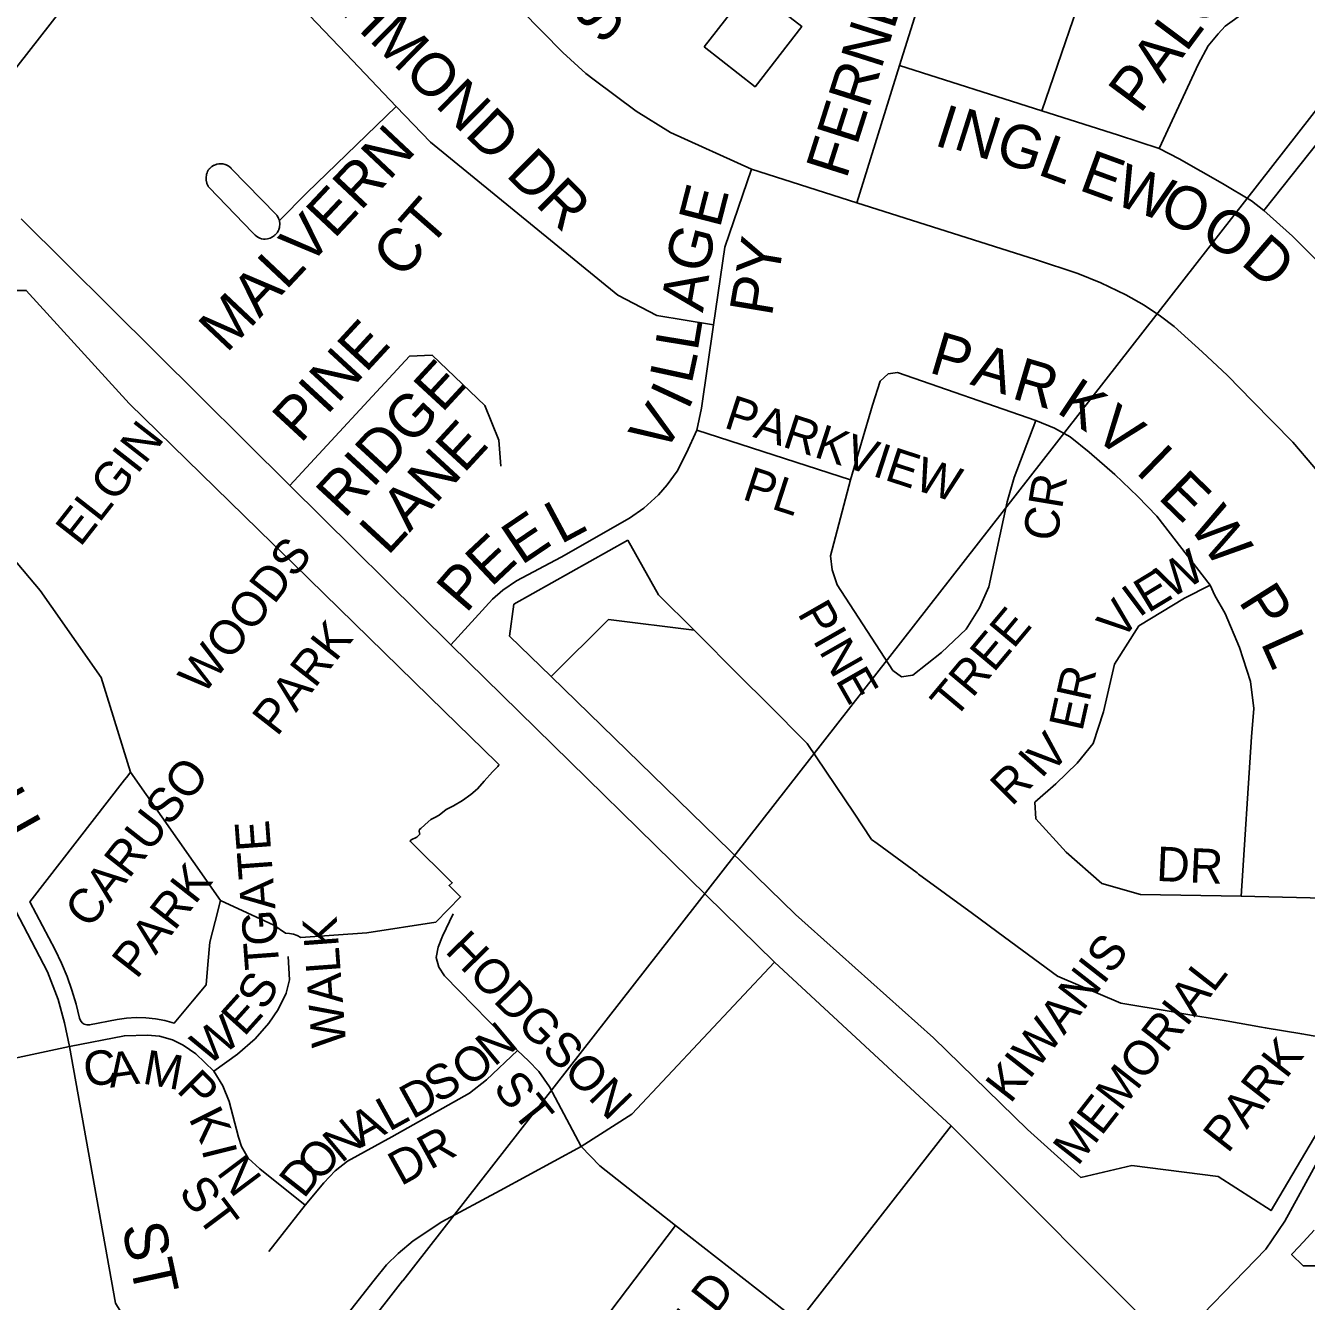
# Model space of a CAD drawing. Extents: x 586326 to 623965, y 4819854 to 4857850.
# Drawn here: x 601295 to 602038, y 4835757 to 4836497 of the extents above; entities that cross this region are included whole.
import ezdxf

# ---------------------------------------------------------------- set-up
doc = ezdxf.new("R2010")
doc.units = 0
for name, color, linetype in [('Lots_Concessions', 7, 'Continuous'), ('Major Rds and Hwys', 7, 'Continuous'), ('Minor Rd Lbls', 7, 'Continuous'), ('Minor Rds', 7, 'Continuous'), ('Park Lbls', 7, 'Continuous'), ('Park Outlines', 7, 'Continuous'), ('Private Rds', 7, 'Continuous'), ('Proposed Secondary Rds', 7, 'Continuous'), ('Pts of Interest', 7, 'Continuous'), ('School Syms_Lbls', 7, 'Continuous')]:
    doc.layers.add(name, color=color, linetype=linetype)

msp = doc.modelspace()

# ---------------------------------------------------------------- linework, layer by layer
at = {"layer": 'Lots_Concessions'}
for p, q in [((601513.73, 4835768.49), (602531.51, 4837073.55)), ((601254.45, 4836428.27), (601404.08, 4836620.12)), ((601396.49, 4835619.72), (601513.66, 4835768.55))]:
    msp.add_line(p, q, dxfattribs=at)
at = {"layer": 'Major Rds and Hwys'}
for points in [[(601292.3, 4836385.14), (601448.1, 4836230.37)], [(601448.1, 4836230.37), (601541.63, 4836137.87)], [(601541.63, 4836137.87), (601729.44, 4835953.61)], [(601729.44, 4835953.61), (601832.04, 4835858.52)], [(601832.04, 4835858.52), (601959.88, 4835730.4)]]:
    msp.add_lwpolyline(points, dxfattribs=at)
at = {"layer": 'Minor Rds'}
for points in [[(601802.14, 4836474.1), (601827.19, 4836554.24), (601837.33, 4836573.34), (601846.44, 4836584.72), (601872.59, 4836606.17), (601883.02, 4836617.63), (601907.63, 4836650.83), (601918.49, 4836667.11), (601922.49, 4836670.84), (601926.59, 4836672.3), (601930.13, 4836672.65), (601933.83, 4836671), (601940.91, 4836665.93), (601977.66, 4836638.47), (601983.35, 4836634.8), (601986.33, 4836632.51), (601987.93, 4836628.32), (601986.86, 4836623.35), (601984.05, 4836617.76), (601973.52, 4836604.41), (601947.37, 4836568.2), (601925.11, 4836549.46), (601914.24, 4836534.33), (601884.63, 4836447.87)], [(601509.99, 4836450.41), (601480.88, 4836480.84), (601425.73, 4836538.84), (601418.98, 4836543.6), (601415.37, 4836549.65), (601413.96, 4836554.17), (601415.4, 4836559.93), (601418.99, 4836564.53), (601424.33, 4836570.05), (601433.48, 4836583.07), (601441.63, 4836592.53), (601457.88, 4836608.42), (601470.85, 4836621.6)], [(601952.74, 4836425.9), (601975.71, 4836475.02), (601981.32, 4836485.58), (601987.1, 4836492.58), (601991.19, 4836497.02), (602015.75, 4836514.71), (602022.71, 4836520.63), (602027.14, 4836526.18), (602051.93, 4836560.15)], [(601777.39, 4836394.4), (601802.14, 4836474.1)], [(601884.63, 4836447.87), (601802.14, 4836474.1)], [(601509.99, 4836450.41), (601458.07, 4836400.27), (601442.12, 4836384.06)], [(601694.09, 4836323.66), (601661.26, 4836329.07), (601638.63, 4836340.85), (601529.77, 4836429.66), (601509.99, 4836450.41)], [(601952.74, 4836425.9), (601929.22, 4836433.77), (601884.63, 4836447.87)], [(602050.99, 4836436.91), (602013.47, 4836390.02)], [(602013.47, 4836390.02), (602006.36, 4836395.52), (601989.56, 4836405.69), (601964.4, 4836419.9), (601952.74, 4836425.9)], [(601442.12, 4836384.06), (601442.21, 4836383.64), (601442.35, 4836382.51), (601442.37, 4836382.3), (601442.37, 4836382.08), (601442.36, 4836381.87), (601442.27, 4836380.73), (601442.24, 4836380.52), (601442.2, 4836380.31), (601442.15, 4836380.11), (601441.81, 4836379.01), (601441.74, 4836378.81), (601441.66, 4836378.62), (601441.56, 4836378.43), (601441, 4836377.43), (601440.88, 4836377.23), (601440.75, 4836377.04), (601440.59, 4836376.86), (601439.7, 4836375.89), (601439.55, 4836375.74), (601439.21, 4836375.46), (601438.08, 4836374.59), (601436.8, 4836373.94), (601435.27, 4836373.52), (601433.84, 4836373.4), (601432.79, 4836373.4), (601431.64, 4836373.52), (601430.68, 4836373.84), (601429.94, 4836374.19), (601429.01, 4836374.79), (601427.96, 4836375.69), (601426.5, 4836377.13), (601401.26, 4836403.23), (601401.11, 4836403.41), (601400.97, 4836403.6), (601400.85, 4836403.8), (601400.74, 4836404.01), (601400.22, 4836405.15), (601400.14, 4836405.33), (601400.08, 4836405.5), (601400.03, 4836405.68), (601399.73, 4836406.91), (601399.69, 4836407.09), (601399.66, 4836407.27), (601399.64, 4836407.46), (601399.57, 4836408.72), (601399.56, 4836408.91), (601399.57, 4836409.09), (601399.59, 4836409.28), (601399.75, 4836410.53), (601399.78, 4836410.71), (601399.82, 4836410.9), (601399.88, 4836411.08), (601400.13, 4836411.86), (601400.43, 4836412.67)], [(601400.43, 4836412.67), (601400.82, 4836413.32), (601401.3, 4836413.96), (601401.41, 4836414.11), (601401.54, 4836414.26), (601401.68, 4836414.4), (601402.47, 4836415.15), (601402.61, 4836415.28), (601402.77, 4836415.4), (601402.93, 4836415.51), (601403.85, 4836416.08), (601404.02, 4836416.18), (601404.19, 4836416.27), (601404.37, 4836416.35), (601405.38, 4836416.74), (601405.57, 4836416.8), (601405.76, 4836416.85), (601405.95, 4836416.89), (601407.02, 4836417.08), (601407.21, 4836417.1), (601407.41, 4836417.12), (601407.6, 4836417.12), (601408.69, 4836417.09), (601408.9, 4836417.08), (601409.12, 4836417.05), (601409.33, 4836417), (601410.58, 4836416.69), (601410.8, 4836416.63), (601411.02, 4836416.55), (601411.23, 4836416.45), (601412.38, 4836415.86), (601412.58, 4836415.74), (601412.78, 4836415.61), (601412.96, 4836415.47), (601413.94, 4836414.63), (601414.05, 4836414.53), (601414.15, 4836414.43), (601440.41, 4836387.39), (601440.56, 4836387.23), (601440.69, 4836387.06), (601440.8, 4836386.89), (601441.4, 4836385.91), (601441.51, 4836385.73), (601441.6, 4836385.54), (601441.68, 4836385.34), (601442.12, 4836384.06)], [(601694.09, 4836323.66), (601700.77, 4836368.76), (601716.13, 4836414)], [(602063.02, 4836341.99), (602030.13, 4836375), (602013.47, 4836390.02)], [(601684.37, 4836262.45), (601687.13, 4836275.28), (601694.09, 4836323.66)], [(601448.1, 4836230.37), (601517.73, 4836305.48), (601530.77, 4836305.93), (601561.32, 4836276.82), (601569.54, 4836256.56), (601570.56, 4836241.53)], [(601881.25, 4836268.06), (601800.96, 4836295.94), (601795.46, 4836295.08), (601790.91, 4836290.91), (601786.47, 4836276.98), (601773.53, 4836233.62)], [(601541.63, 4836137.87), (601565.78, 4836164.27), (601571.75, 4836169.5), (601579.74, 4836174.89), (601605.65, 4836188.68), (601645.33, 4836211.36), (601653.67, 4836217.2), (601662.27, 4836224.92), (601667.21, 4836230.62), (601672.92, 4836238.67), (601678.4, 4836249.22), (601684.37, 4836262.45)], [(601773.53, 4836233.62), (601684.37, 4836262.45)], [(601881.25, 4836268.06), (601868.66, 4836234.99), (601864.62, 4836220.76), (601853.85, 4836171.51), (601848.48, 4836159.28), (601840.77, 4836146.94), (601826.54, 4836133.26), (601809.88, 4836120.18), (601803.31, 4836119.2), (601798.15, 4836122.9), (601765.83, 4836172.64), (601762.95, 4836181.33), (601761.94, 4836189.49), (601773.53, 4836233.62)], [(601982.44, 4836172.49), (601951.39, 4836212.46), (601940.33, 4836223.95), (601926.97, 4836236.68), (601912.11, 4836249.6), (601901.06, 4836258.57), (601892, 4836263.54), (601881.25, 4836268.06)], [(602000.35, 4835991.95), (601942.01, 4835992.87), (601919.5, 4835999.3), (601898.75, 4836017.47), (601881.13, 4836036.76), (601880.71, 4836046.41), (601892.86, 4836057.19), (601905.26, 4836069.13), (601914.45, 4836080.61), (601920.41, 4836098.9), (601926.85, 4836126.55), (601941, 4836148.8), (601967.48, 4836164.83), (601982.44, 4836172.49)], [(602000.35, 4835991.95), (602006.33, 4836084.29), (602007.7, 4836100.83), (602005.87, 4836116.45), (601999.44, 4836136.2), (601991.17, 4836155.95), (601985.19, 4836166.52), (601982.44, 4836172.49)], [(601277.3, 4836005.5), (601307.49, 4835947.86), (601313.77, 4835931.85), (601317.29, 4835918.25), (601320.26, 4835904.69)], [(602096.64, 4835989.53), (602000.35, 4835991.95)], [(601580.25, 4835902.34), (601537.94, 4835945.67), (601534.74, 4835950.72), (601533.05, 4835956.28), (601534.27, 4835962.24), (601536.86, 4835968.59), (601542.99, 4835981.65)], [(601404.01, 4835890.29), (601417.76, 4835900.13), (601428.04, 4835908.97), (601435.95, 4835918.06), (601441.43, 4835926.01), (601445.97, 4835935.63), (601448.03, 4835943.39), (601447.13, 4835956.86)], [(601218.4, 4835822.4), (601271.18, 4835890.01), (601275.12, 4835893.44), (601279.54, 4835895.85), (601320.26, 4835904.69)], [(601320.26, 4835904.69), (601352.19, 4835910.87), (601365.55, 4835911.14), (601372.52, 4835910.56), (601380.06, 4835908.55), (601386.32, 4835905.4), (601393.58, 4835900.31), (601404.01, 4835890.29)], [(601320.26, 4835904.69), (601346.95, 4835755.54), (601358.93, 4835735.95), (601374.57, 4835721.63), (601426.32, 4835680)], [(601580.25, 4835902.34), (601562.26, 4835885.33), (601552.38, 4835877.57), (601507.46, 4835852.17), (601481.62, 4835838.11), (601474.39, 4835832.33), (601467.84, 4835825.43), (601457.02, 4835812.57)], [(601617.3, 4835846.52), (601598.95, 4835881.1), (601592.63, 4835890.15), (601586.76, 4835896.29), (601580.25, 4835902.34)], [(601404.01, 4835890.29), (601409.35, 4835881.79), (601412.86, 4835872.65), (601418.35, 4835851.89), (601420.2, 4835846.57), (601424.07, 4835839.86), (601430.74, 4835833.56), (601457.02, 4835812.57)], [(601457.02, 4835812.57), (601435.96, 4835785.61)]]:
    msp.add_lwpolyline(points, dxfattribs=at)
at = {"layer": 'Park Outlines'}
for points in [[(601213.66, 4836275.56), (601303.16, 4836169.35), (601309.62, 4836160.16), (601338.72, 4836118.75), (601343.93, 4836101.98), (601355.77, 4836063.91), (601392, 4836012.09), (601407.93, 4835989.32), (601438.98, 4835975.03), (601445.62, 4835970.31), (601447.97, 4835970.23), (601450.28, 4835969.78), (601452.48, 4835968.97), (601454.54, 4835967.83), (601492.94, 4835970.6), (601532.85, 4835976.88), (601547.27, 4835991.46), (601540.61, 4835997.99), (601542.44, 4835999.71), (601517.95, 4836023.72), (601518.65, 4836024.51), (601521.87, 4836026.19), (601523.59, 4836027.81), (601523.27, 4836029.46), (601523.29, 4836029.89), (601523.51, 4836030.6), (601524.13, 4836031.17), (601526.49, 4836033.33), (601526.79, 4836033.58), (601530.1, 4836036.31), (601532.37, 4836037.54), (601534.87, 4836038.88), (601538.89, 4836042.15), (601543.23, 4836044.36), (601548.32, 4836047.38), (601553.23, 4836050.83), (601557.02, 4836054.24), (601560.91, 4836058.72), (601565.76, 4836064.08), (601568.84, 4836067.23), (601569.25, 4836067.72), (601569.64, 4836068.16), (601568.34, 4836069.44), (601537.65, 4836099.42), (601450.65, 4836184.43), (601438.37, 4836196.43), (601354.94, 4836277.96), (601295.21, 4836343.53), (601274.76, 4836343.46)], [(602059.83, 4835907.77), (602035.52, 4835911.92), (602014.36, 4835915.54), (602012.24, 4835915.9), (601991.65, 4835919.42), (601965.9, 4835923.82), (601962.87, 4835924.34), (601959.84, 4835924.85), (601930.53, 4835929.86), (601893.72, 4835945.48), (601863.09, 4835968.03), (601844.36, 4835981.8), (601813.18, 4836004.73), (601812.3, 4836005.38), (601789.06, 4836022.48), (601785.87, 4836024.82), (601775.69, 4836039.99), (601748.42, 4836080.6), (601725.23, 4836103.87), (601709.84, 4836119.28), (601682.88, 4836146.27), (601633.22, 4836152.51), (601599.91, 4836119.32), (601666.03, 4836055.01), (601741.66, 4835981.27), (601749.11, 4835974.6), (601821.76, 4835909.61), (601876.29, 4835856.41), (601907.36, 4835828.6), (601936.89, 4835835.43), (601987.07, 4835829.13), (602017.74, 4835809.3), (602074.45, 4835905.29)], [(602042.78, 4835797.89), (602036.65, 4835791.15), (602030.3, 4835784.61), (602029.62, 4835783.94), (602036.48, 4835777.21), (602123.18, 4835777.21)]]:
    msp.add_lwpolyline(points, dxfattribs=at)
for points in [[(601644.31, 4836198.64), (601578.28, 4836161.31), (601575.74, 4836142.82), (601599.91, 4836119.32), (601633.22, 4836152.51), (601682.88, 4836146.27), (601662.19, 4836166.9)], [(601355.23, 4836063.22), (601353.3, 4836060.77), (601352.27, 4836059.44), (601297.3, 4835988.63), (601311.87, 4835960.67), (601315.56, 4835953.08), (601318.83, 4835945.3), (601321.67, 4835937.35), (601324.08, 4835929.26), (601326.05, 4835921.05), (601326.6, 4835919.61), (601327.56, 4835918.4), (601328.85, 4835917.54), (601330.34, 4835917.12), (601331.89, 4835917.18), (601347.86, 4835920.28), (601353.39, 4835921.11), (601358.98, 4835921.46), (601364.58, 4835921.32), (601370.14, 4835920.71), (601375.63, 4835919.62), (601381.01, 4835918.06), (601391.65, 4835930.94), (601399.53, 4835940.5), (601400.6, 4835952.19), (601401.79, 4835965.16), (601404.86, 4835977.24), (601407.93, 4835989.32), (601392, 4836012.09), (601355.77, 4836063.91)]]:
    msp.add_lwpolyline(points, close=True, dxfattribs=at)
at = {"layer": 'Private Rds'}
for points in [[(601832.04, 4835858.52), (601743.37, 4835744.92)], [(601672, 4835800.68), (601628.12, 4835835.23), (601617.3, 4835846.52)], [(601672, 4835800.68), (601527.22, 4835609.68)], [(601743.37, 4835744.92), (601672, 4835800.68)]]:
    msp.add_lwpolyline(points, dxfattribs=at)
at = {"layer": 'Proposed Secondary Rds'}
for points in [[(601716.13, 4836414), (601669.19, 4836435.31), (601649.13, 4836447.65), (601624.84, 4836465.87), (601620.04, 4836469.47), (601606.67, 4836481.59), (601570.24, 4836518.91)], [(601777.39, 4836394.4), (601716.13, 4836414)], [(602054.88, 4836225.63), (602042.53, 4836241.1), (602030.47, 4836255.46), (602006.89, 4836279.27), (601992.42, 4836294.07), (601977.83, 4836307.96), (601961.48, 4836322.6), (601953.64, 4836328.58), (601944.04, 4836334.92), (601933.41, 4836341.04), (601918.92, 4836348), (601905.68, 4836353.4), (601881.03, 4836361.6), (601777.39, 4836394.4)], [(601729.44, 4835953.61), (601646.7, 4835865.34), (601617.3, 4835846.52)], [(601959.88, 4835730.4), (602014.71, 4835786.88), (602025.66, 4835803.23), (602045.61, 4835839.57), (602069.04, 4835878.86)], [(601617.3, 4835846.52), (601570.22, 4835821.03), (601536.44, 4835802.85), (601519.84, 4835791.78), (601511.05, 4835784.5), (601504.26, 4835777.79), (601497.11, 4835768.91), (601479.25, 4835746.39), (601426.32, 4835680)]]:
    msp.add_lwpolyline(points, dxfattribs=at)
at = {"layer": 'School Syms_Lbls'}
msp.add_lwpolyline([(601688.59, 4836484.91), (601715.86, 4836519.81), (601745.47, 4836496.68), (601718.2, 4836461.78)], close=True, dxfattribs=at)

# ---------------------------------------------------------------- texts
at = {"layer": 'Minor Rd Lbls'}
for s, height, rotation, p in [('PALGRAVE', 25.002, 53.3103, (601941.81, 4836445.54)), ('FERNDALE', 25.002, 72.39239, (601771.17, 4836407.69)), ('RICHMOND DR', 25.002, 315.35589, (601435.48, 4836546.1)), ('I', 25, 342.3499, (601821.48, 4836428.1)), ('N', 25, 342.3499, (601832.48, 4836426.1)), ('G', 25, 342.3499, (601856.48, 4836419.1)), ('MALVERN', 25.002, 46.73434, (601411.48, 4836306.74)), ('L', 25, 339.94392, (601881.48, 4836411.1)), ('E', 25, 339.94392, (601905.48, 4836402.1)), ('W', 25, 339.94392, (601925.48, 4836394.1)), ('E', 25, 75.61862, (601697.72, 4836379.12)), ('O', 25, 336.57133, (601951.48, 4836385.1)), ('CT', 25.002, 48.71593, (601513.03, 4836349.45)), ('O', 25, 326.88868, (601975.48, 4836374.1)), ('G', 25, 75.61862, (601689.75, 4836352.6)), ('PY', 25.002, 80.48687, (601727.9, 4836327.9)), ('D', 25, 319.26791, (601999.48, 4836359.1)), ('A', 25, 80.15651, (601687.9, 4836330.36)), ('PINE', 25.002, 47.29063, (601454.4, 4836254.24)), ('L', 25, 80.6111, (601684.86, 4836307.81)), ('P', 25, 343.54, (601818.48, 4836296.1)), ('L', 25, 77.79745, (601681.32, 4836288.65)), ('A', 25, 343.54, (601842.48, 4836289.1)), ('RIDGE', 25.002, 47.29063, (601479.77, 4836210.56)), ('R', 25, 343.54, (601866.48, 4836281.1)), ('K', 25, 326.30995, (601892.48, 4836273.1)), ('I', 25, 65.03111, (601679.26, 4836273.38)), ('V', 25, 56.49266, (601664.74, 4836247.69)), ('PARKVIEW', 19.998, 341.99586, (601699.48, 4836264.1)), ('V', 25, 322.52384, (601913.48, 4836259.1)), ('LANE', 25.002, 47.29063, (601505.05, 4836189.1)), ('I', 25, 315.85512, (601938.48, 4836238.1)), ('PL', 19.998, 341.99586, (601710.13, 4836222.56)), ('E', 25, 315.85512, (601951.48, 4836223.1)), ('CR', 19.998, 80.5377, (601893.22, 4836197.15)), ('L', 25, 28.17861, (601605.34, 4836195.94)), ('W', 25, 304.59231, (601969.48, 4836207.1)), ('E', 25, 34.08782, (601582.63, 4836183.69)), ('E', 25, 43.28438, (601564.95, 4836170.78)), ('W', 20, 31.21842, (601959.14, 4836164.11)), ('P', 25, 49.14464, (601550.4, 4836155.56)), ('E', 20, 31.21842, (601946.28, 4836155.96)), ('I', 20, 36.86992, (601941.15, 4836153.25)), ('P', 25, 302.19575, (601998.48, 4836163.1)), ('V', 19.96, 50.86992, (601930.78, 4836139.5)), ('PINE', 19.998, 299.7449, (601742.48, 4836156.1)), ('TREE', 19.998, 50.10981, (601833.88, 4836093.91)), ('L', 25, 294.22776, (602011.48, 4836139.1)), ('R', 19.99, 77.47121, (601912.37, 4836104.22)), ('E', 19.99, 77.47121, (601908.15, 4836087.05)), ('MILL', 25.002, 299.29138, (601251.48, 4836078.1)), ('V', 20, 48.94521, (601889.89, 4836062.11)), ('I', 20, 48.94521, (601884.41, 4836059.57)), ('R', 20, 45.00002, (601867.13, 4836043.58)), ('GATE', 19.998, 94.23641, (601441.36, 4835963.88)), ('DR', 19.998, 357.43078, (601950.87, 4836000.77)), ('WALK', 19.998, 94.23641, (601480.92, 4835904.92)), ('HODGSON', 19.998, 314.32598, (601537.63, 4835959.61)), ('T', 20, 94.23641, (601442.19, 4835949.91)), ('S', 20, 60.25514, (601433.83, 4835924.81)), ('E', 20, 48.01281, (601421.59, 4835909.85)), ('W', 20, 35.5377, (601400.28, 4835893.11)), ('N', 20, 39.80559, (601566.79, 4835892.47)), ('O', 20, 40.60131, (601552.66, 4835880.33)), ('C', 20, 8.88068, (601330.01, 4835880.89)), ('A', 20, 8.13012, (601343.83, 4835880.63)), ('M', 20, 349.69517, (601362.07, 4835883.22)), ('P', 20, 315.00002, (601381.82, 4835878.75)), ('S', 20, 30.96378, (601533.99, 4835871.27)), ('ST', 19.998, 308.65983, (601565.48, 4835880.34)), ('D', 20, 28.96768, (601519.35, 4835862.12)), ('L', 20, 28.96768, (601505.73, 4835854.92)), ('K', 20, 296.56507, (601389.11, 4835862.93)), ('A', 20, 28.96768, (601489.79, 4835845.85)), ('N', 20, 39.80559, (601478.09, 4835836.43)), ('DR', 19.998, 28.96768, (601512.68, 4835823.35)), ('I', 20, 284.03626, (601396.84, 4835844.99)), ('O', 20, 51.91125, (601466.12, 4835825.24)), ('N', 20, 306.86992, (601405.18, 4835831.41)), ('D', 20, 51.91125, (601456.26, 4835815.72)), ('ST', 19.998, 306.86992, (601383, 4835820.06)), ('ST', 25.002, 282.18865, (601350.48, 4835800.1))]:
    msp.add_text(s, height=height, rotation=rotation, dxfattribs=at).set_placement(p)
at = {"layer": 'Park Lbls'}
for s, p in [('ELGIN', (601326.54, 4836194.11)), ('WOODS', (601397.86, 4836108.09)), ('PARK', (601440.72, 4836084.05)), ('CARUSO', (601331.85, 4835972.26)), ('PARK', (601359.24, 4835943.18)), ('KIWANIS', (601866.41, 4835870.91)), ('MEMORIAL', (601905.52, 4835834.66)), ('PARK', (601992.64, 4835842.01))]:
    msp.add_text(s, height=19.992, rotation=52.00002, dxfattribs=at).set_placement(p)
at = {"layer": 'Pts of Interest'}
msp.add_text('SHOPPERS WORLD', height=19.992, rotation=52.00002, dxfattribs=at).set_placement((601550.09, 4835562.41))
at = {"layer": 'School Syms_Lbls'}
msp.add_text('ST.FRANCIS', height=25, rotation=52.00002, dxfattribs=at).set_placement((601630.31, 4836485.29))

doc.saveas('drawing.dxf')
